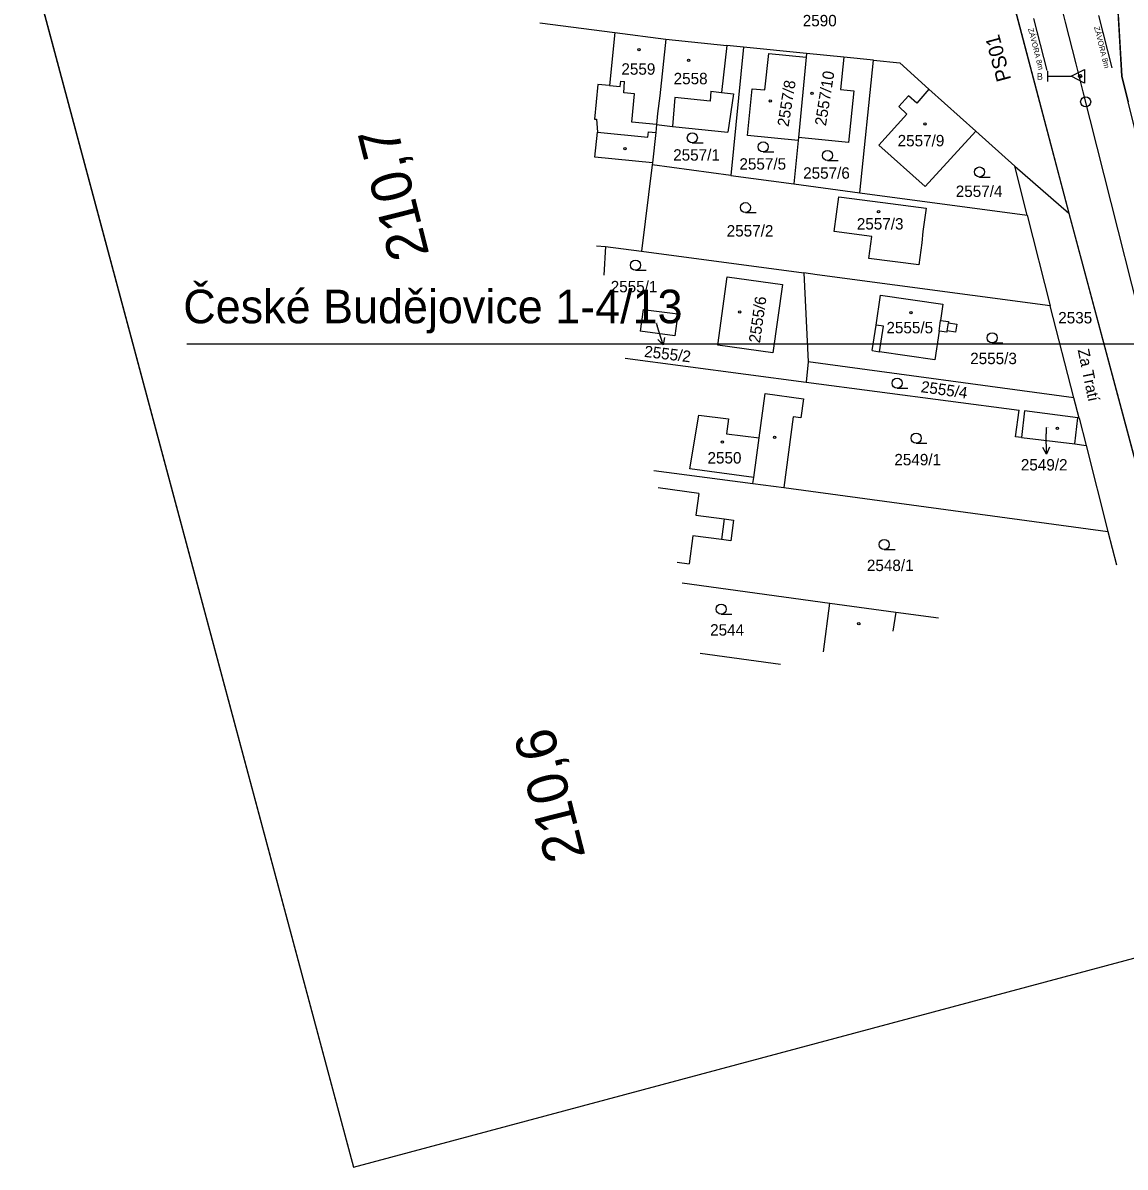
# Model space of a CAD drawing. Extents: x -754710 to -754206, y -1169123 to -1168234.
# Drawn here: x -754541.8 to -754377.7, y -1169122.6 to -1168952.2 of the extents above; entities that cross this region are included whole.
import ezdxf

# ---------------------------------------------------------------- set-up
doc = ezdxf.new("R2010")
doc.units = 0
for name, color, linetype in [('Vrstva 1', 7, 'Continuous'), ('Vrstva 15', 7, 'Continuous'), ('Vrstva 16', 7, 'Continuous'), ('Vrstva 18', 7, 'Continuous'), ('Vrstva 19', 7, 'Continuous'), ('Vrstva 25', 7, 'Continuous'), ('Vrstva 3', 7, 'Continuous'), ('Vrstva 4', 7, 'Continuous'), ('Vrstva 61', 7, 'Continuous'), ('Vrstva 7', 7, 'Continuous')]:
    doc.layers.add(name, color=color, linetype=linetype)

msp = doc.modelspace()

# ---------------------------------------------------------------- linework, layer by layer
at = {"layer": 'Vrstva 1'}
for p, q in [((-754379.05, -1168945.33), (-754378.16, -1168960.13)), ((-754394.57, -1168948.26), (-754386.06, -1168980.52)), ((-754391.33, -1168951.52), (-754389.35, -1168959.27)), ((-754381.64, -1168951.09), (-754379.68, -1168958.85)), ((-754464.85, -1168952.18), (-754453.68, -1168953.61)), ((-754453.68, -1168953.61), (-754454.48, -1168961.5)), ((-754453.68, -1168953.61), (-754446.09, -1168954.58)), ((-754446.09, -1168954.58), (-754446.98, -1168963.03)), ((-754446.09, -1168954.58), (-754437, -1168955.53)), ((-754437, -1168955.53), (-754437.78, -1168962.52)), ((-754434.53, -1168955.78), (-754437, -1168955.53)), ((-754434.53, -1168955.78), (-754436.38, -1168974.88)), ((-754425.12, -1168956.72), (-754434.53, -1168955.78)), ((-754431.33, -1168962.16), (-754430.76, -1168956.72)), ((-754430.76, -1168956.72), (-754425.18, -1168957.29)), ((-754425.12, -1168956.72), (-754425.18, -1168957.29)), ((-754419.59, -1168957.27), (-754425.12, -1168956.72)), ((-754425.18, -1168957.29), (-754426.34, -1168969.24)), ((-754419.59, -1168957.27), (-754420.07, -1168962.07)), ((-754415.14, -1168957.72), (-754419.59, -1168957.27)), ((-754417.17, -1168977.46), (-754415.14, -1168957.72)), ((-754415.14, -1168957.72), (-754411.25, -1168958.11)), ((-754411.25, -1168958.11), (-754406.9, -1168962.02)), ((-754378.16, -1168960.13), (-754377.23, -1168963.95)), ((-754456.19, -1168961.34), (-754456.71, -1168966.5)), ((-754454.48, -1168961.5), (-754456.19, -1168961.34)), ((-754446.98, -1168963.03), (-754447.3, -1168965.65)), ((-754437.78, -1168962.52), (-754436.02, -1168962.72)), ((-754436.02, -1168962.72), (-754436.82, -1168968.44)), ((-754433.91, -1168968.96), (-754433.24, -1168962)), ((-754433.24, -1168962), (-754431.33, -1168962.16)), ((-754420.07, -1168962.07), (-754418.08, -1168962.31)), ((-754418.08, -1168962.31), (-754418.86, -1168969.98)), ((-754409.93, -1168963.02), (-754411.4, -1168964.64)), ((-754408.69, -1168964.11), (-754409.93, -1168963.02)), ((-754406.9, -1168962.02), (-754408.69, -1168964.11)), ((-754406.9, -1168962.02), (-754399.92, -1168968.29)), ((-754411.4, -1168964.64), (-754410.19, -1168965.77)), ((-754456.71, -1168966.5), (-754456.41, -1168966.53)), ((-754456.41, -1168966.53), (-754456.27, -1168968.44)), ((-754447.3, -1168965.65), (-754447.44, -1168967.3)), ((-754410.19, -1168965.77), (-754414.34, -1168970.38)), ((-754456.63, -1168972.16), (-754456.27, -1168968.44)), ((-754447.56, -1168968.51), (-754448.05, -1168973.02)), ((-754447.44, -1168967.3), (-754447.56, -1168968.51)), ((-754447.44, -1168967.3), (-754445.06, -1168967.58)), ((-754445.06, -1168967.58), (-754436.82, -1168968.44)), ((-754407.44, -1168976.53), (-754399.92, -1168968.29)), ((-754399.92, -1168968.29), (-754394.13, -1168973.5)), ((-754426.39, -1168969.71), (-754433.91, -1168968.96)), ((-754426.39, -1168969.71), (-754427.02, -1168976.13)), ((-754426.34, -1168969.24), (-754426.39, -1168969.71)), ((-754418.86, -1168969.98), (-754426.34, -1168969.24)), ((-754414.34, -1168970.38), (-754407.44, -1168976.53)), ((-754448.05, -1168973.02), (-754456.63, -1168972.16)), ((-754448.09, -1168973.3), (-754449.71, -1168986.17)), ((-754448.05, -1168973.02), (-754448.09, -1168973.3)), ((-754436.38, -1168974.88), (-754448.09, -1168973.3)), ((-754394.13, -1168973.5), (-754386.06, -1168980.52)), ((-754392.28, -1168980.8), (-754394.13, -1168973.5)), ((-754436.38, -1168974.88), (-754427.02, -1168976.13)), ((-754427.02, -1168976.13), (-754418.28, -1168977.31)), ((-754418.28, -1168977.31), (-754417.17, -1168977.46)), ((-754421.01, -1168983.23), (-754420.33, -1168978.08)), ((-754420.33, -1168978.08), (-754413.76, -1168978.94)), ((-754417.17, -1168977.46), (-754392.28, -1168980.8)), ((-754413.76, -1168978.94), (-754407.29, -1168979.79)), ((-754407.29, -1168979.79), (-754407.79, -1168983.26)), ((-754386.06, -1168980.52), (-754372.58, -1169030.98)), ((-754392.28, -1168980.8), (-754388.85, -1168994.33)), ((-754415.4, -1168983.97), (-754421.01, -1168983.23)), ((-754415.84, -1168987.24), (-754415.4, -1168983.97)), ((-754407.79, -1168983.26), (-754407.98, -1168984.94)), ((-754456.4, -1168985.39), (-754455.05, -1168985.5)), ((-754455.05, -1168985.5), (-754455.29, -1168989.75)), ((-754455.05, -1168985.5), (-754449.71, -1168986.17)), ((-754407.98, -1168984.94), (-754408.42, -1168988.22)), ((-754449.71, -1168986.17), (-754425.52, -1168989.41)), ((-754408.42, -1168988.22), (-754415.84, -1168987.24)), ((-754438.33, -1169000.18), (-754436.92, -1168989.99)), ((-754436.92, -1168989.99), (-754428.72, -1168991.13)), ((-754425.52, -1168989.41), (-754424.88, -1169002.68)), ((-754423.54, -1168989.68), (-754425.52, -1168989.41)), ((-754388.85, -1168994.33), (-754423.54, -1168989.68)), ((-754428.72, -1168991.13), (-754430.14, -1169001.31)), ((-754414.78, -1168997.18), (-754414.13, -1168992.71)), ((-754414.13, -1168992.71), (-754404.82, -1168994.06)), ((-754404.82, -1168994.06), (-754405.17, -1168996.48)), ((-754385.31, -1169008.03), (-754388.85, -1168994.33)), ((-754449.45, -1168994.84), (-754449.88, -1168998.11)), ((-754449.45, -1168994.84), (-754444.3, -1168995.53)), ((-754444.3, -1168995.53), (-754444.71, -1168998.76)), ((-754415.33, -1169000.99), (-754414.78, -1168997.18)), ((-754405.17, -1168996.48), (-754403.97, -1168996.66)), ((-754403.97, -1168996.66), (-754404, -1168996.86)), ((-754404, -1168996.86), (-754402.76, -1168997.04)), ((-754402.76, -1168997.04), (-754402.95, -1168998.23)), ((-754444.71, -1168998.76), (-754449.88, -1168998.11)), ((-754405.4, -1168998.07), (-754406.03, -1169002.37)), ((-754404.22, -1168998.25), (-754405.4, -1168998.07)), ((-754404.19, -1168998.06), (-754404.22, -1168998.25)), ((-754402.95, -1168998.23), (-754404.19, -1168998.06)), ((-754430.14, -1169001.31), (-754438.33, -1169000.18)), ((-754415.33, -1169000.99), (-754414.24, -1169001.17)), ((-754406.03, -1169002.37), (-754414.24, -1169001.17)), ((-754452.14, -1169002.13), (-754425.19, -1169005.68)), ((-754424.88, -1169002.68), (-754425.19, -1169005.68)), ((-754385.31, -1169008.03), (-754424.88, -1169002.68)), ((-754425.19, -1169005.68), (-754393.45, -1169009.86)), ((-754432.17, -1169013.97), (-754431.27, -1169007.35)), ((-754431.27, -1169007.35), (-754425.59, -1169008.18)), ((-754425.59, -1169008.18), (-754425.97, -1169010.98)), ((-754384.54, -1169011.03), (-754385.31, -1169008.03)), ((-754442.51, -1169018.57), (-754441.18, -1169010.6)), ((-754441.18, -1169010.6), (-754436.76, -1169011.15)), ((-754436.76, -1169011.15), (-754437.04, -1169013.4)), ((-754427.11, -1169010.83), (-754428.52, -1169021.39)), ((-754425.97, -1169010.98), (-754427.11, -1169010.83)), ((-754394.01, -1169013.82), (-754393.45, -1169009.86)), ((-754392.65, -1169009.96), (-754393.13, -1169013.93)), ((-754384.71, -1169011.01), (-754392.65, -1169009.96)), ((-754385.17, -1169014.89), (-754384.71, -1169011.01)), ((-754384.54, -1169011.03), (-754383.51, -1169015.1)), ((-754437.04, -1169013.4), (-754432.17, -1169013.97)), ((-754393.13, -1169013.93), (-754394.01, -1169013.82)), ((-754393.13, -1169013.93), (-754385.17, -1169014.89)), ((-754385.17, -1169014.89), (-754383.51, -1169015.1)), ((-754383.51, -1169015.1), (-754380.27, -1169027.93)), ((-754447.88, -1169018.84), (-754433.1, -1169020.78)), ((-754432.97, -1169019.86), (-754442.51, -1169018.57)), ((-754433.1, -1169020.78), (-754432.97, -1169019.86)), ((-754441.16, -1169022.27), (-754447.23, -1169021.41)), ((-754433.1, -1169020.78), (-754428.52, -1169021.39)), ((-754428.52, -1169021.39), (-754380.27, -1169027.93)), ((-754441.16, -1169022.27), (-754441.59, -1169025.49)), ((-754441.59, -1169025.49), (-754437.41, -1169026.05)), ((-754437.41, -1169026.05), (-754435.98, -1169026.24)), ((-754435.98, -1169026.24), (-754436.39, -1169029.3)), ((-754380.27, -1169027.93), (-754378.98, -1169032.89)), ((-754442.04, -1169028.55), (-754442.6, -1169032.74)), ((-754437.79, -1169029.11), (-754442.04, -1169028.55)), ((-754436.39, -1169029.3), (-754437.79, -1169029.11)), ((-754444.41, -1169032.47), (-754442.6, -1169032.74)), ((-754443.62, -1169035.58), (-754421.64, -1169038.61)), ((-754422.62, -1169045.87), (-754421.64, -1169038.61)), ((-754421.64, -1169038.61), (-754411.85, -1169039.94)), ((-754411.85, -1169039.94), (-754412.29, -1169042.79)), ((-754411.85, -1169039.94), (-754405.49, -1169040.77)), ((-754428.98, -1169047.76), (-754440.95, -1169046.08))]:
    msp.add_line(p, q, dxfattribs=at)
for points in [[(-754367.04, -1169029.33), (-754371.5, -1169011.68), (-754383.94, -1168962.43), (-754384.99, -1168958.29), (-754386.56, -1168952.08), (-754387.62, -1168947.84), (-754397.03, -1168910.64), (-754410.17, -1168858.68)], [(-754394.57, -1168948.26), (-754386.06, -1168980.52), (-754372.58, -1169030.98), (-754361.7, -1169027.75), (-754366.06, -1169009.68), (-754368.41, -1168999.96), (-754369.4, -1168995.91), (-754373.54, -1168979.01), (-754377.23, -1168963.95), (-754378.16, -1168960.13), (-754379.05, -1168945.33)]]:
    msp.add_lwpolyline(points, dxfattribs=at)
msp.add_circle((-754383.57, -1168963.93), 0.75, dxfattribs=at)
at = {"layer": 'Vrstva 16'}
for p, q in [((-754447.5, -1168996.9), (-754447.38, -1168997.27)), ((-754446.45, -1169000.12), (-754447.38, -1168997.27)), ((-754389.47, -1169012.45), (-754389.46, -1169013.39)), ((-754389.42, -1169016.39), (-754389.46, -1169013.39))]:
    msp.add_line(p, q, dxfattribs=at)
for points in [[(-754446.29, -1168999.02), (-754446.45, -1169000.12), (-754447.24, -1168999.33)], [(-754388.93, -1169015.38), (-754389.42, -1169016.39), (-754389.93, -1169015.4)]]:
    msp.add_lwpolyline(points, dxfattribs=at)
at = {"layer": 'Vrstva 25'}
for p, q in [((-754442.13, -1168970.05), (-754440.53, -1168970.05)), ((-754431.59, -1168971.4), (-754429.99, -1168971.4)), ((-754422.01, -1168972.66), (-754420.41, -1168972.66)), ((-754399.38, -1168975.13), (-754397.78, -1168975.13)), ((-754434.23, -1168980.43), (-754432.63, -1168980.43)), ((-754450.59, -1168989.01), (-754448.99, -1168989.01)), ((-754397.49, -1168999.83), (-754395.89, -1168999.83)), ((-754411.65, -1169006.59), (-754410.05, -1169006.59)), ((-754408.81, -1169014.78), (-754407.21, -1169014.78)), ((-754413.55, -1169030.62), (-754411.95, -1169030.62)), ((-754437.84, -1169040.23), (-754436.24, -1169040.23))]:
    msp.add_line(p, q, dxfattribs=at)
for centre, radius in [((-754450.08, -1168956.15), 0.175), ((-754442.68, -1168957.75), 0.175), ((-754430.52, -1168963.79), 0.175), ((-754424.29, -1168962.67), 0.175), ((-754407.51, -1168967.22), 0.175), ((-754442.13, -1168969.3), 0.75), ((-754431.59, -1168970.65), 0.75), ((-754452.17, -1168970.92), 0.175), ((-754422.01, -1168971.91), 0.75), ((-754399.38, -1168974.38), 0.75), ((-754434.23, -1168979.68), 0.75), ((-754414.41, -1168980.27), 0.175), ((-754450.59, -1168988.26), 0.75), ((-754435.08, -1168995.22), 0.175), ((-754409.59, -1168995.31), 0.175), ((-754397.49, -1168999.08), 0.75), ((-754411.65, -1169005.84), 0.75), ((-754387.77, -1169012.56), 0.175), ((-754437.65, -1169014.6), 0.175), ((-754429.87, -1169013.89), 0.175), ((-754408.81, -1169014.03), 0.75), ((-754413.55, -1169029.87), 0.75), ((-754437.84, -1169039.48), 0.75), ((-754417.34, -1169041.65), 0.175)]:
    msp.add_circle(centre, radius, dxfattribs=at)
at = {"layer": 'Vrstva 3'}
msp.add_lwpolyline([(-754710.01, -1168311.22), (-754492.6, -1169122.6), (-754205.72, -1169045.73), (-754423.13, -1168234.35)], close=True, dxfattribs=at)
msp.add_lwpolyline([(-754375, -1168707.79), (-754375, -1169000), (-754517.39, -1169000)], dxfattribs=at)
at = {"layer": 'Vrstva 4'}
for p, q in [((-754389.23, -1168959.35), (-754389.23, -1168960.9)), ((-754384.56, -1168959.91), (-754384.22, -1168960.26)), ((-754454.48, -1168961.5), (-754452.87, -1168961.66)), ((-754452.87, -1168961.66), (-754452.79, -1168960.85)), ((-754452.79, -1168960.85), (-754452.21, -1168960.92)), ((-754452.35, -1168962.61), (-754452.21, -1168960.92)), ((-754450.76, -1168962.75), (-754452.35, -1168962.61)), ((-754451.12, -1168966.98), (-754450.76, -1168962.75)), ((-754444.75, -1168963.26), (-754445.06, -1168967.58)), ((-754439.48, -1168963.81), (-754444.75, -1168963.26)), ((-754439.39, -1168962.34), (-754439.48, -1168963.81)), ((-754439.39, -1168962.34), (-754437.78, -1168962.52)), ((-754447.44, -1168967.3), (-754451.12, -1168966.98)), ((-754456.27, -1168968.44), (-754448.74, -1168969.19)), ((-754448.74, -1168969.19), (-754448.66, -1168968.4)), ((-754448.66, -1168968.4), (-754447.56, -1168968.51)), ((-754413.68, -1168997.34), (-754414.78, -1168997.18)), ((-754414.24, -1169001.17), (-754413.68, -1168997.34)), ((-754405.4, -1168998.07), (-754405.17, -1168996.48)), ((-754404.19, -1168998.06), (-754404, -1168996.86)), ((-754432.97, -1169019.86), (-754432.17, -1169013.97)), ((-754437.41, -1169026.05), (-754437.79, -1169029.11))]:
    msp.add_line(p, q, dxfattribs=at)
msp.add_lwpolyline([(-754389.23, -1168960.13), (-754385.75, -1168960.12), (-754383.75, -1168959.13), (-754383.74, -1168961.13), (-754385.75, -1168960.12)], dxfattribs=at)
msp.add_circle((-754384.39, -1168960.09), 0.248, dxfattribs=at)
at = {"layer": 'Vrstva 61'}
msp.add_line((-754710.01, -1168311.22), (-754492.6, -1169122.6), dxfattribs=at)
msp.add_lwpolyline([(-754492.6, -1169122.6), (-754205.72, -1169045.73), (-754423.13, -1168234.35), (-754710.01, -1168311.22)], dxfattribs=at)

# ---------------------------------------------------------------- texts
at = {"layer": 'Vrstva 15'}
msp.add_text('Za Tratí', height=1.7, rotation=281.7233, dxfattribs=at).set_placement((-754384.76, -1169000.89))
at = {"layer": 'Vrstva 16'}
msp.add_text('2555/2', height=1.7, rotation=353.1712, dxfattribs=at).set_placement((-754449.36, -1169001.91))
msp.add_text('2549/2', height=1.7, dxfattribs=at).set_placement((-754393.22, -1169018.84))
at = {"layer": 'Vrstva 18'}
for s, height, p in [('2590', 1.7, (-754425.69, -1168952.68)), ('2557/1', 1.7, (-754444.98, -1168972.69)), ('2557/5', 1.7, (-754435.12, -1168974.03)), ('2557/6', 1.7, (-754425.63, -1168975.38)), ('2557/4', 1.7, (-754402.91, -1168978.1)), ('2557/2', 1.7, (-754437.01, -1168983.99)), ('2555/1', 1.7, (-754454.28, -1168992.3)), ('2535', 1.7, (-754387.65, -1168996.93)), ('2555/2', 0.1, (-754447.76, -1168996.9)), ('2555/3', 1.7, (-754400.76, -1169003)), ('2549/1', 1.7, (-754412.05, -1169018.07)), ('2548/1', 1.7, (-754416.14, -1169033.82)), ('2544', 1.7, (-754439.48, -1169043.43))]:
    msp.add_text(s, height=height, dxfattribs=at).set_placement(p)
msp.add_text('2555/4', height=1.7, rotation=351.9107, dxfattribs=at).set_placement((-754408.18, -1169007.16))
at = {"layer": 'Vrstva 19'}
for s, height, p in [('2559', 1.7, (-754452.69, -1168959.89)), ('2558', 1.7, (-754444.91, -1168961.31)), ('2557/9', 1.7, (-754411.56, -1168970.56)), ('2557/3', 1.7, (-754417.64, -1168982.95)), ('2555/5', 1.7, (-754413.23, -1168998.41)), ('2549/2', 0.1, (-754389.46, -1169012.45)), ('2550', 1.7, (-754439.87, -1169017.8))]:
    msp.add_text(s, height=height, dxfattribs=at).set_placement(p)
for s, rotation, p in [('2557/10', 81.0162, (-754422.24, -1168967.59)), ('2557/8', 81.0162, (-754427.81, -1168967.72)), ('2555/6', 81.8757, (-754432.06, -1168999.92))]:
    msp.add_text(s, height=1.7, rotation=rotation, dxfattribs=at).set_placement(p)
at = {"layer": 'Vrstva 3'}
msp.add_text('PS01', height=2.16, rotation=105, dxfattribs=at).set_placement((-754394.65, -1168960.58))
msp.add_text('České Budějovice 1-4/13', height=5, dxfattribs=at).set_placement((-754517.92, -1168996.91))
at = {"layer": 'Vrstva 4'}
for rotation, p in [(284.325, (-754392.15, -1168953.06)), (284.134, (-754382.32, -1168952.81))]:
    msp.add_text('ZÁVORA 8m', height=0.8, rotation=rotation, dxfattribs=at).set_placement(p)
msp.add_text('B', height=1, dxfattribs=at).set_placement((-754390.83, -1168960.65))
at = {"layer": 'Vrstva 7'}
for s, rotation, p in [('210,7', 104.1774, (-754481.27, -1168986.63)), ('210,6', 104.1922, (-754458.02, -1169076.27))]:
    msp.add_text(s, height=6, rotation=rotation, dxfattribs=at).set_placement(p)

doc.saveas('drawing.dxf')
